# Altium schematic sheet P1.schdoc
size 297 x 209 mm; Symbol: Drawing-Symbol_A4; Company: 嘉立创EDA; Version: V1.0; Page Size: A4; @Project Name: 远程开机卡; @Update Date: 2026-06-18; @Create Date: 2026-06-18; Device: Drawing-Symbol_A4; @Board Name: cm4; @Page Name: P1; @Create Time: 07:18:48; @Page Count: 7; @Page No: 7; @Schematic Name: Schematic3_7; @Update Time: 07:18:48; @Assembly Variant: Basic; Border: 1; Title Block Position: 3; Size: A4; Width: 1170; Height: 825; Region Start: 1; X Region Count: 6; Y Region Count: 4; Blade Width: 10
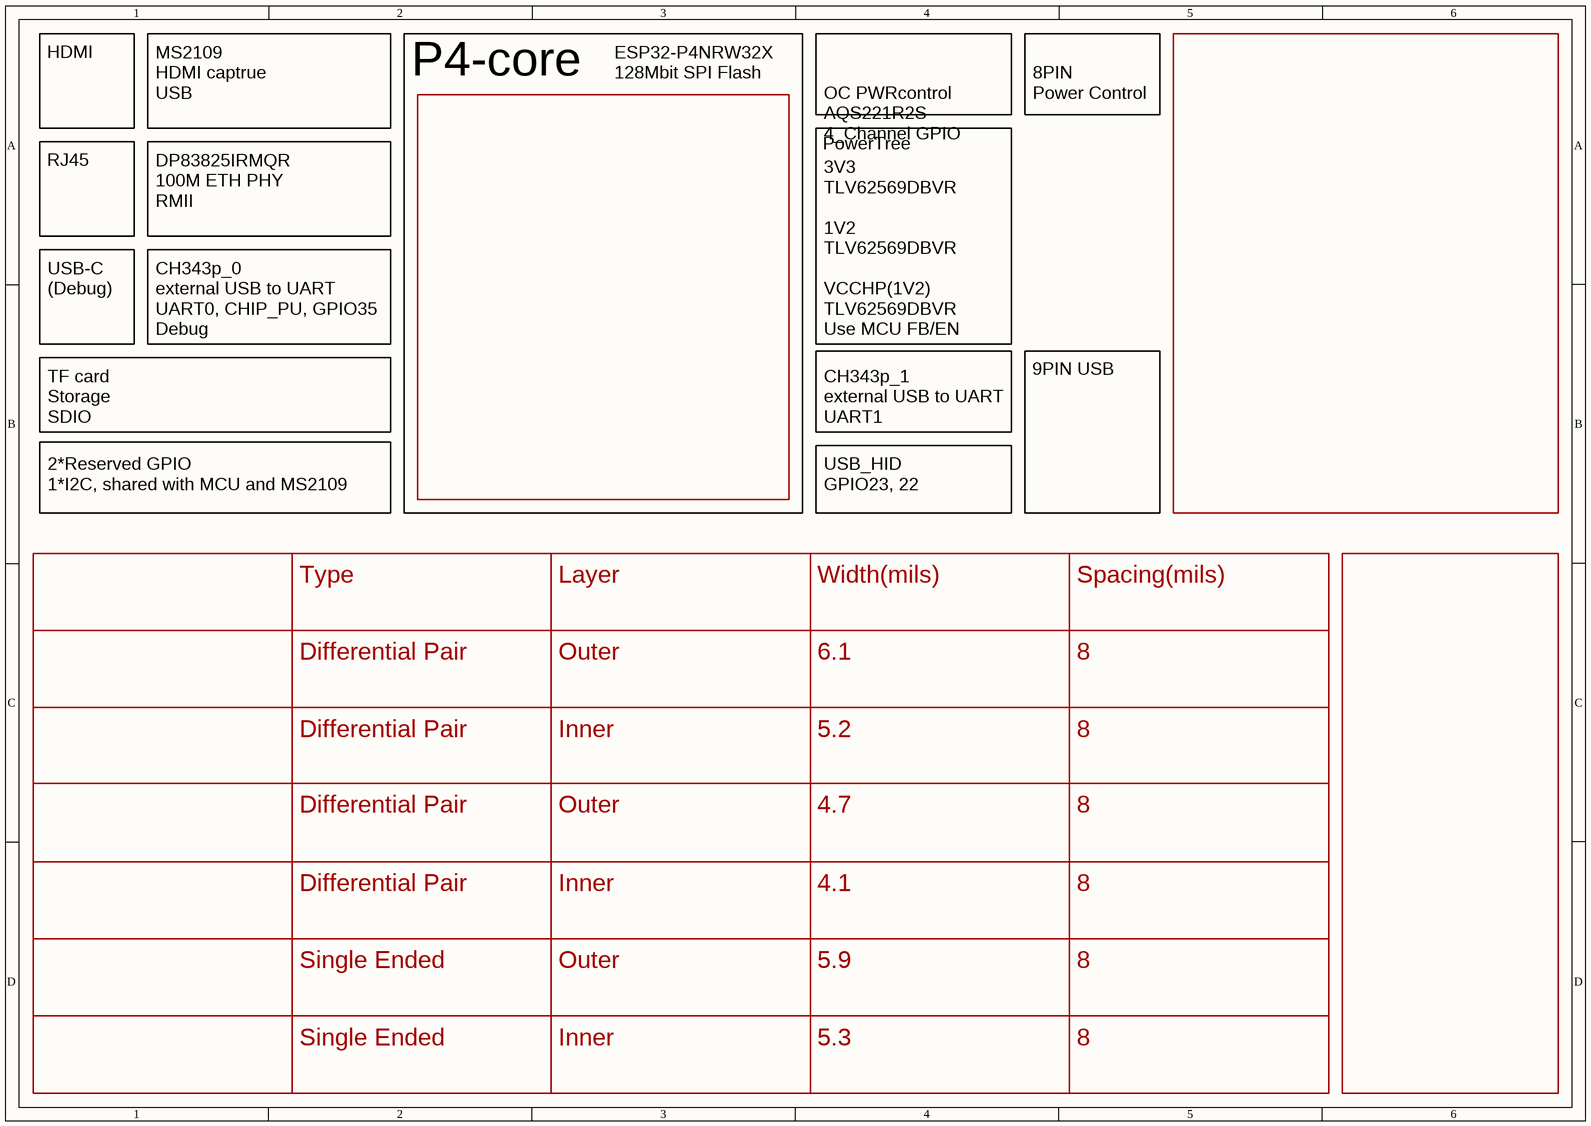
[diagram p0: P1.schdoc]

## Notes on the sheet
- HDMI
- MS2109
  HDMI captrue
  USB
- ESP32-P4NRW32X
  128Mbit SPI Flash
- 8PIN
  Power Control
- P4-core
- OC PWRcontrol
  AQS221R2S
  4_Channel GPIO
- RJ45
- DP83825IRMQR
  100M ETH PHY
  RMII
- PowerTree
- 3V3
  TLV62569DBVR
  1V2
  TLV62569DBVR
  VCCHP(1V2)
  TLV62569DBVR
  Use MCU FB/EN
- USB-C
  (Debug)
- CH343p_0
  external USB to UART
  UART0, CHIP_PU, GPIO35
  Debug
- TF card
  Storage
  SDIO
- CH343p_1
  external USB to UART
  UART1
- 9PIN USB
- 2*Reserved GPIO
  1*I2C, shared with MCU and MS2109
- USB_HID
  GPIO23, 22
- Type
- Layer
- Width(mils)
- Spacing(mils)
- Differential Pair
- Outer
- 6.1
- 8
- Inner
- 5.2
- 4.7
- 4.1
- Single Ended
- 5.9
- 5.3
